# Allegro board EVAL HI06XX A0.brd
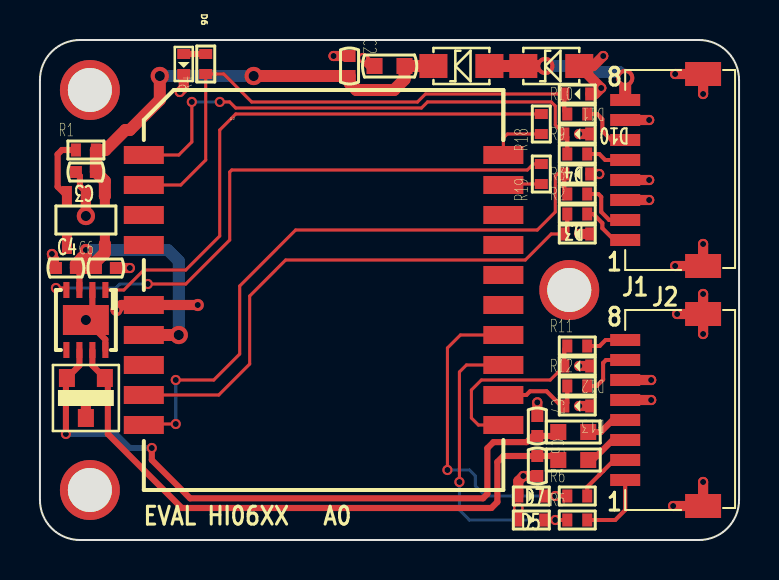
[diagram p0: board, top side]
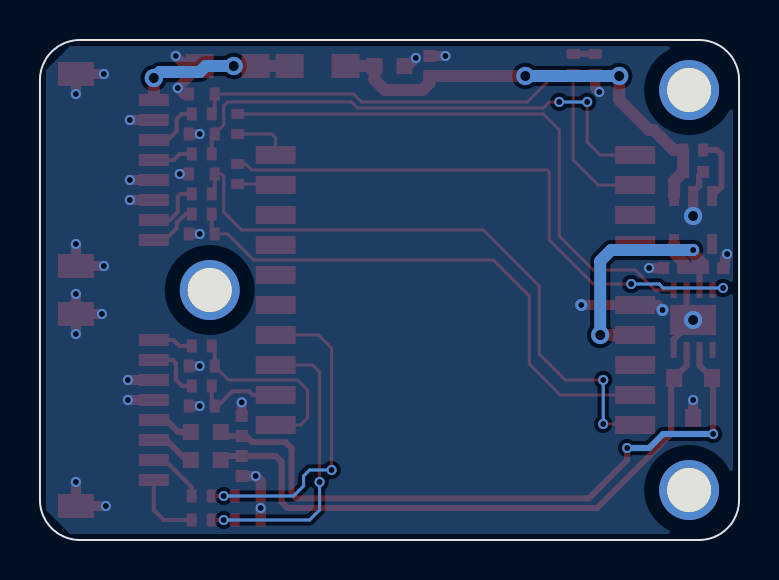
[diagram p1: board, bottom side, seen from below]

Outline 35 x 25 mm; copper layers: TOP, BOTTOM. Coordinates in mm from the lower left corner of the outline.
Outline path: 0,23 0,2 arc(0.59,0.59) 2,0 33,0 arc(34.41,0.59) 35,2 35,23 arc(34.41,24.41) 33,25 2,25 arc(0.59,24.41) 0,23

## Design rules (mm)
constraint set DEFAULT: min track width 0.152
net group CAN2: nets H L

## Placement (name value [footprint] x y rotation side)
C1  10uF  [C0603]  17.5 23.7 0 top
C2  0.1uF  [C0402]  15.5 23.7 270 top
C3  1uF  [C0402]  2.3 18.4 180 top
C4  1uF  [C0402]  1.3 13.6 0 top
C5  100pF  [C0402]  24.9 3.7 270 top
C6  0.1uF  [C0402]  3.3 13.6 0 top
C7  100pF  [C0402]  24.9 5.7 270 top
D1  1N5819  [SOD123FL]  21.1 23.7 0 top
D2  SDD32A05L01  [SOD123FL]  25.6 23.7 0 top
D3  SBD52C05L01  [SOD-523]  26.9 15.3 180 top
D4  SBD52C05L01  [SOD-523]  26.9 18.3 180 top
D5  SBD52C05L01  [SOD-523]  24.6 1 0 top
D6  GREEN  [LED0402]  7.2 23.8 270 top
D7  SBD52C05L01  [SOD-523]  24.6 2.2 0 top
D10  SBD52C05L01  [SOD-523]  26.9 20.3 180 top
D11  SBD52C05L01  [SOD-523]  26.9 22.3 180 top
D12  SBD52C05L01  [SOD-523]  26.9 8.7 180 top
D13  SBD52C05L01  [SOD-523]  26.9 6.7 180 top
D18  SM24CANB-02HTG  [SOT23-3-0_95]  2.3 7.1 180 top
F1  100mA  [F0603]  26.7 4 180 top
F2  100mA  [F0603]  26.7 5.4 180 top
H1  HOLE  [HOLE-2-MM]  2.5 22.5 0 top
H2  HOLE  [HOLE-2-MM]  2.5 2.5 0 top
H3  HOLE  [HOLE-2-MM]  26.5 12.5 0 top
J1  CON10  [5015680807_1]  29.3 18.5 270 top
J2  CON10  [5015680807_1]  29.3 6.5 270 top
R1  1K  [R0402]  2.3 19.5 0 top
R2  33R  [R0402]  26.9 16.3 0 top
R3  33R  [R0402]  26.9 17.3 0 top
R4  510R  [R0402]  8.3 23.8 90 top
R5  33R  [R0402]  26.9 1 0 top
R6  33R  [R0402]  26.9 2.2 0 top
R9  33R  [R0402]  26.9 19.3 0 top
R10  33R  [R0402]  26.9 21.3 0 top
R11  33R  [R0402]  26.9 9.7 0 top
R12  33R  [R0402]  26.9 7.7 0 top
R18  1K  [R0402]  25.1 20.8 90 top
R19  1K  [R0402]  25.1 18.3 90 top
U1  SPX3819M5-L-3-3/TR  [SOT23-5-0_95]  2.3 16 180 top
U2  HI06XX-MI0  [HI06]  14.2 12.5 0 top
U3  SIT3051TK  [HVSON8]  2.3 11 270 top

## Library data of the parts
C1-C7 = Capacity_Nonpolarity
D1 = diode
D2-D5 D7 D10-D13 = DIODE BI-DIR TRIG
D6 = LED
D18 = BAT54A/SOT
F1 F2 = Fuse
H1-H3 = HOLE
J1 J2 = CON10
R1-R6 R9-R12 R18 R19 = Res
U1 = XC6210
U2 = HI05-MI0
U3 = SIT3051TK

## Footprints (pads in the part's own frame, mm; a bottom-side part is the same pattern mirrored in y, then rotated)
5015680807_1
  rect 0.6x1.5 smd: 1(3.5,0) 2(2.5,0) 3(1.5,0) 4(0.5,0) 5(-0.5,0) 6(-1.5,0) 7(-2.5,0) 8(-3.5,0)
  rect 1.2x1.8 smd: 9(4.8,3.9) 10(-4.8,3.9)
C0402
  rect 0.6x0.6 smd: 1(-0.5,0) 2(0.5,0)
C0603
  rect 0.8x0.8 smd: 1(-0.75,0) 2(0.75,0)
F0603
  rect 0.8x0.8 smd: 1(-0.75,0) 2(0.75,0)
HI06
  rect 2x0.9 smd: 1(-9,6.75) 2(-9,5.25) 3(-9,3.75) 4(-9,2.25) 5(-9,-0.75) 6(-9,-2.25) 7(-9,-3.75) 8(-9,-5.25) 9(-9,-6.75) 10(9,-6.75) 11(9,-5.25) 12(9,-3.75) 13(9,-2.25) 14(9,-0.75) 15(9,0.75) 16(9,2.25) 17(9,3.75) 18(9,5.25) 19(9,6.75)
HOLE-2-MM
  round 3 hole 2.2: 1(0,0)
HVSON8
  rect 0.8x0.3 smd: 1(-1.5,0.975) 2(-1.5,0.325) 3(-1.5,-0.325) 4(-1.5,-0.975) 5(1.5,-0.975) 6(1.5,-0.325) 7(1.5,0.325) 8(1.5,0.975)
  rect 1.5x2.3 smd: 9(0,0)
LED0402
  rect 0.5x0.65 smd: 1(-0.5,0) 2(0.5,0)
R0402
  rect 0.5x0.65 smd: 1(-0.5,0) 2(0.5,0)
SOD123FL
  rect 1.4x1.2 smd: 1(1.4,0) 2(-1.4,0)
SOD-523
  rect 0.5x0.65 smd: 1(-0.65,0) 2(0.65,0)
SOT23-3-0_95
  rect 0.8x0.9 smd: 1(-0.95,-1) 2(0.95,-1) 3(0,1)
SOT23-5-0_95
  rect 0.5x1 smd: 1(-0.95,-1.2) 2(0,-1.2) 3(0.95,-1.2) 4(0.95,1.2) 5(-0.95,1.2)

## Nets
5V: D1.1(P) D2.2 J1.8
GND: C1.1 C2.1 C3.2 C4.1 C5.2 C6.2 C7.1 D2.1 D3.1 D4.1 D5.1 D6.2(-) D7.1 D10.1 D11.1 D12.1 D13.1 D18.3 J1.3 J1.4 J1.7 J1.9 J1.10 J2.5 J2.6 J2.9 J2.10 U1.2(VSS) U2.5 U3.2 U3.8 U3.9
VCC: C1.2 C2.2 C3.1 D1.2 R1.2 U1.1
CAN_RX: R19.1 U2.18
CAN_TX: R18.1 U2.19
CS: U2.14
DP3V3: C4.2 C6.1 U1.5 U2.6(VDD) U3.3(VCC)
H: F1.1 J2.3
L: F2.1 J2.4
MISO: U2.16
MOSI: U2.17
RST: U2.7
RXD1: D4.2 R3.1 U2.9
RXD2: D7.2 R6.1 U2.13
RXD3/SDA2: D13.2 R12.1 U2.11
RXD4: U2.4
SCK: U2.15
SIN/PPS: J1.5 R9.2
SOUT: J1.6 R10.2
SYNC_IN/PPS: D10.2 R9.1 U2.1
SYNC_OUT: D11.2 R4.1 R10.1 U2.2
TXD1: D3.2 R2.1 U2.8
TXD2: D5.2 R5.1 U2.12
TXD3/SCL2: D12.2 R11.1 U2.10
TXD4: U2.3
USART1_RX: J1.2 R3.2
USART1_TX: J1.1 R2.2
USART2_RX: J2.2 R6.2
USART2_TX: J2.1 R5.2
USART3_RX: J2.7 R12.2
USART3_TX: J2.8 R11.2
N2198535: D6.1 R4.2
N2224750: R1.1 U1.3
N2242059: C5.1 D18.1 F1.2 U3.7
N2242241: R18.2 U3.1
N2242331: C7.2 D18.2 F2.2 U3.6
N2242381: R19.2 U3.4

Pads without a net: H1 1; H2 1; H3 1; U1 4; U3 5

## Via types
v1: diameter 0.508, hole 0.305, TOP to BOTTOM, 42 vias
v2: diameter 0.914, hole 0.508, TOP to BOTTOM, 7 vias
v3: diameter 0.61, hole 0.305, TOP to BOTTOM, 3 vias

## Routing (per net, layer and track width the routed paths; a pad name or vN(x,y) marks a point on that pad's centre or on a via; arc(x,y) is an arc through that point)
5V: length 8.1
  TOP w0.6: D1.1 D2.2 v2(25.3,23.7) ; J1.8 v2(29.3,23.1)
  BOTTOM w0.6: v2(29.3,23.1) 29,23.4 27,23.4 26.7,23.7 v2(25.3,23.7)
GND: length 41.5
  TOP w0.305: U1.2 2.3,17.4 2,17.7 2,18.2 C3.2 ; U3.8 3.27,10.02 v2(2.3,11) 2.62,11.32 U3.2
  TOP w0.508: v1(31.7,1.7) J2.9 v1(33.2,2.9) ; J2.10 v1(31.9,11.3) ; J2.10 v1(33.2,10.3) ; J2.10 v1(33.2,12.3) ; v1(31.8,13.7) J1.9 v1(33.2,14.8) ; D10.1 v1(27,20.3) ; D4.1 v1(28,18.3) ; C4.1 0.7,13.7 0.7,14.05 0.64,14.11 0.64,14.26 v1(0.6,14.3) ; J1.3 v1(30.5,17) ; C6.2 v1(4.5,13.6) ; C2.1 v1(14.7,24.2) ; J2.5 v1(30.6,7) ; D3.1 v1(27,15.3) ; v1(33.2,22.3) J1.10 v1(31.8,23.3) ; C5.2 v1(24.2,3.2) 23.95,2.95 D7.1 ; C1.1 16.58,23.7 v1(16.18,24.1) ; D12.1 v1(27,8.7) ; v1(28.2,24.2) 27.7,23.7 D2.1 v1(28.1,22.6) 27.8,22.3 D11.1 ; D18.3 v1(2.3,7) ; D13.1 v1(27,6.7) ; J1.4 v1(30.5,18) ; J1.7 v1(30.5,21) ; D5.1 v1(23.95,1.6) ; v3(7.9,11.75) U2.5 4.08,11.75 v3(3.83,11.5) ; D6.2 7.2,22.6 v1(7,22.4) ; J2.6 v1(30.6,8) ; U1.2 v2(2.3,16.2) ; C7.1 v1(24.9,6.88)
VCC: length 23
  TOP w0.6: v2(6,23.2) 6,22 4.5,20.5 4.28,20.5 3.28,19.5 R1.2 C3.1 3.25,17.95 U1.1 ; D1.2 C1.2 18.25,23.02 17.73,22.5 15.85,22.5 15.5,22.85 C2.2 v2(10.7,23.2)
  BOTTOM w0.6: v2(10.7,23.2) v2(6,23.2)
CAN_RX: length 1.9
  TOP w0.152: U2.18 23.25,17.8 R19.1
CAN_TX: length 2.8
  TOP w0.152: U2.19 23.2,20.1 23.4,20.3 R18.1
DP3V3: length 15
  TOP w0.305: C4.2 1.98,13.42 U3.3
  TOP w0.6: U2.6 v2(6.95,10.25) ; U1.5 3.25,14.36 2.8,13.91 C6.1 C4.2 1.8,13.79 2.1,14.09 2.1,14.11 2.3,14.3 v3(2.3,14.5)
  BOTTOM w0.6: v2(6.95,10.25) 6.95,13.95 6.4,14.5 v3(2.3,14.5)
H: length 2.3
  TOP w0.305: J2.3 28.68,5 27.68,4 F1.1
L: length 2.1
  TOP w0.305: F2.1 28.08,5.4 28.68,6 J2.4
RXD1: length 31.6
  TOP w0.152: U2.9 5.25,5.8 v1(6.8,5.8) ; v1(6.8,8) 8.7,8 10,9.3 10,12.7 12.8,15.5 24.9,15.5 25.8,16.4 25.8,18.2 25.9,18.3 D4.2
  TOP w0.203: D4.2 26.25,17.45 R3.1
  BOTTOM w0.152: v1(6.8,8) v1(6.8,5.8)
RXD2: length 16.6
  TOP w0.152: U2.13 21.05,10.25 20.4,9.6 v1(20.4,3.5)
  TOP w0.203: R6.1 v1(25.8,2.2) D7.2
  BOTTOM w0.152: v1(20.4,3.5) 21.5,3.5 21.8,3.2 21.8,2.7 22.3,2.2 v1(25.8,2.2)
RXD3/SDA2: length 4.5
  TOP w0.203: U2.11 24.35,7.25 24.54,7.44 25.36,7.44 26.1,6.7 D13.2 26.4,6.85 R12.1
SIN/PPS: length 2
  TOP w0.203: R9.2 28,19.3 28.3,19 J1.5
SOUT: length 2.8
  TOP w0.203: J1.6 28.6,20 28.16,20.44 28.16,21.04 27.9,21.3 R10.2
SYNC_IN/PPS: length 25.9
  TOP w0.152: D10.2 25.8,20.75 25.8,21.7 25.6,21.9 19.4,21.9 19.1,21.6 9.8,21.6 9.5,21.9 v1(9,21.9) ; U2.1 6.95,19.25 7.6,19.9 v1(7.6,21.9)
  TOP w0.203: D10.2 26.4,20.15 R9.1
  BOTTOM w0.152: v1(9,21.9) v1(7.6,21.9)
SYNC_OUT: length 27.7
  TOP w0.152: U2.2 7.05,17.75 8.3,19 R4.1 9.2,23.3 10.6,21.9 18.9,21.9 19.3,22.3 D11.2
  TOP w0.203: D11.2 26.25,21.45 R10.1
TXD1: length 27.4
  TOP w0.152: U2.8 8.95,7.25 10.5,8.8 10.5,12.2 12.3,14 24.3,14 25.6,15.3 D3.2
  TOP w0.203: R2.1 26.4,15.45 D3.2
TXD2: length 15.4
  TOP w0.152: v1(21,2.9) 21,8.4 21.35,8.75 U2.12
  TOP w0.203: D5.2 v1(25.8,1) R5.1
  BOTTOM w0.152: v1(21,2.9) 21,1.5 21.5,1 v1(25.8,1)
TXD3/SCL2: length 9.4
  TOP w0.152: D12.2 25.55,8 22.1,8 21.6,7.5 21.6,6.1 21.95,5.75 U2.10
  TOP w0.203: R11.1 26.25,9.55 D12.2
USART1_RX: length 2.9
  TOP w0.203: R3.2 27.96,17.3 28.1,17.16 28.1,16.4 28.5,16 J1.2
USART1_TX: length 2.6
  TOP w0.203: J1.1 28.75,15 28.16,15.59 28.16,15.84 27.7,16.3 R2.2
USART2_RX: length 2.9
  TOP w0.203: R6.2 27.4,2.65 27.99,3.24 28,3.24 28.21,3.45 28.21,3.46 28.75,4 J2.2
USART2_TX: length 3.6
  TOP w0.203: R5.2 28.8,1 29.3,1.5 J2.1
USART3_RX: length 2.9
  TOP w0.203: R12.2 27.87,7.7 28.19,8.02 28.19,8.86 28.34,9 J2.7
USART3_TX: length 2
  TOP w0.203: R11.2 28.02,9.7 28.32,10 J2.8
N2198535: length 1.1
  TOP w0.305: D6.1 R4.2
N2224750: length 3.3
  TOP w0.305: R1.1 1.1,19.5 0.88,19.28 0.88,17.67 U1.3
N2242059: length 30.9
  TOP w0.305: F1.2 25.75,4.2 C5.1 23.2,4.2 22.9,3.9 22.9,1.9 22.6,1.6 7.1,1.6 3.4,5.3 3.4,7.95 D18.1 2.62,8.73 U3.7
N2242241: length 28.6
  TOP w0.152: U3.1 4.2,12.5 5.2,13.5 7.3,13.5 9,15.2 9,20.5 9.8,21.3 R18.2
N2242331: length 33.5
  TOP w0.305: v1(1.3,5.3) 1.3,8.05 D18.2 1.98,8.73 U3.6 ; F2.2 25.75,5.2 C7.2 24.67,5.2 24.37,4.89 22.7,4.89 22.4,4.59 22.4,2.3 22.18,2.08 7.52,2.08 5.6,4 v1(5.6,4.6)
  BOTTOM w0.305: v1(5.6,4.6) 4.5,4.6 3.8,5.3 v1(1.3,5.3)
N2242381: length 29.4
  TOP w0.152: v1(0.8,12.6) 1.22,12.6 U3.4 ; R19.2 24.7,18.8 24.4,18.5 9.6,18.5 9.5,18.4 9.5,15 7.3,12.8 v1(5.4,12.8)
  BOTTOM w0.152: v1(0.8,12.6) 3.8,12.6 4,12.8 v1(5.4,12.8)

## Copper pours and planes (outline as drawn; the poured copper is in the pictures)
GND on BOTTOM: 1.8,24.7 33.5,24.7 34.7,23.5 34.7,1.5 33.5,0.3 1.7,0.3 0.3,1.7 0.3,23.2

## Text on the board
Ref Des/Silkscreen Top: EVAL HI06XX | A0 | 8 | 1 | J1 | J2
User.8: FIGURE | FINISHED_SIZE | 10.0 | 12.0 | 20.0 | 86.614 | DRILL CHART: TOP to BOTTOM | ALL UNITS ARE IN MILS | PLATED | QTY | 126 | 2 | 3
